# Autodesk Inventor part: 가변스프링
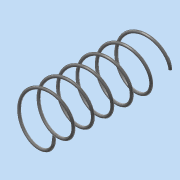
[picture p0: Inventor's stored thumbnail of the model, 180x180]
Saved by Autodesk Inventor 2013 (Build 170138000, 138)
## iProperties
Created: 2016-11
Part Number: 가변스프링
Material: 강철, 탄소
Document SubType Name: Modeling
Designer: dgall
Density: 1 g/cm^3
Author: dgall
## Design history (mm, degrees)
sketch "스케치1"
  geometry: L1 (0, 0)-(16, 0); L2 (0, 0)-(0, 84.368); L3 (0, 84.368)-(16, 84.368); C1 r 1 at (16, 0)
  constraints: 6 end point, 2 perpendicular, 1 centre point, 1 coincident, 1 horizontal, 1 vertical alignment
  dimensions: "d0" = 84.36759 distance of L1.start L2.end (derived); "d1" = 32 diameter of L3.end L2; "d2" = 2 diameter of C1
feature "코일1" sketch "스케치1" pitch "d3" = 10; turns "d5" = 6; dims "d4" = 84.36759 (= d0), "d6" = 0, angle "d7" = 90 deg, angle "d8" = 90 deg, "d9" = 0, "d10" = 0
feature "분할1"
node "작업 평면1"
feature "분할2"
node "솔리드1"
